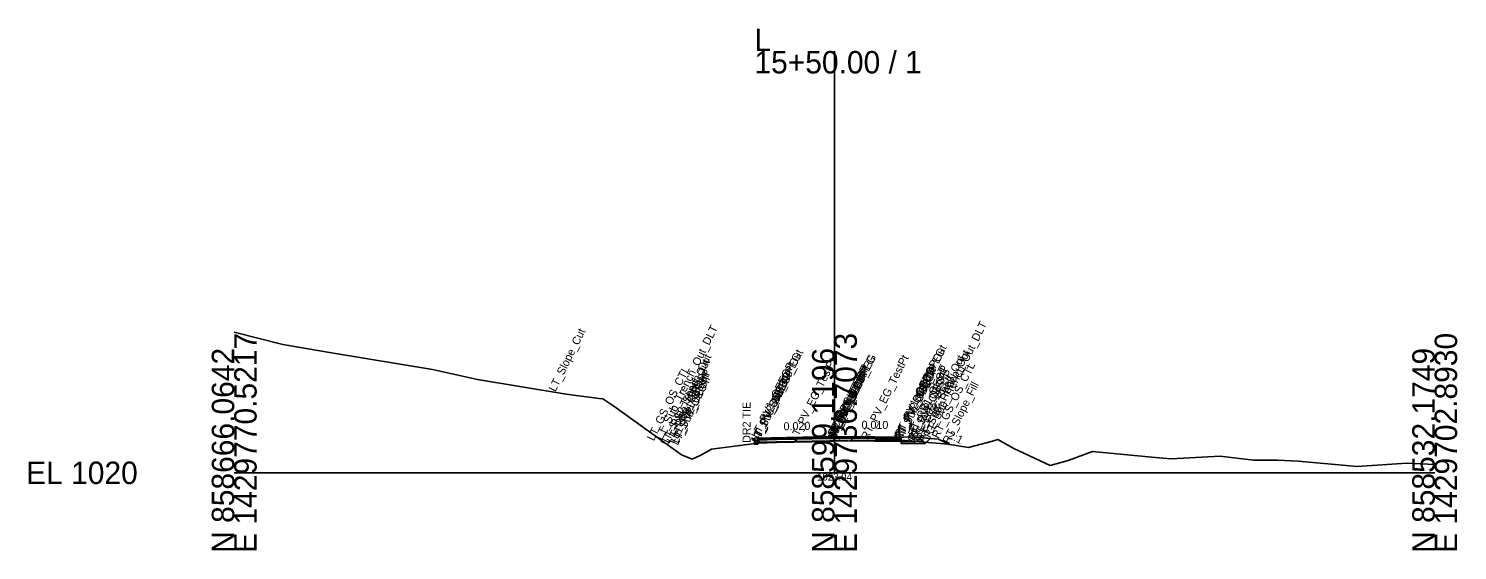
# Model space of a CAD drawing. Extents: x -26 to 153, y -10 to 13058.
# Drawn here: x -25.7 to 152.8, y 7990.3 to 8055.5 of the extents above; entities that cross this region are included whole.
import ezdxf

# ---------------------------------------------------------------- set-up
doc = ezdxf.new("R2010")
doc.units = 0
for name, color, linetype in [('Default', 7, 'Continuous'), ('Exist Cross Section Cell', 7, 'Continuous'), ('Exist XS Center Line Elevation Label', 7, 'Continuous'), ('Exist XS Ground Line', 7, 'Continuous'), ('Prop CMT Pvmt Course 1', 7, 'Continuous'), ('Prop CMT Pvmt Course 1 Wedge', 7, 'Continuous'), ('Prop CMT Pvmt Course 2', 7, 'Continuous'), ('Prop CMT Pvmt Course 2 Wedge', 7, 'Continuous'), ('Prop CMT Pvmt Surface', 7, 'Continuous'), ('Prop CMT Pvmt Surface Shoulder', 7, 'Continuous'), ('Prop CMT Pvmt Wedge Surface 1', 7, 'Continuous'), ('Prop CMT Pvmt Wedge Surface 2', 7, 'Continuous'), ('Prop CMT Shld Paved Course 1', 7, 'Continuous'), ('Prop CMT Shld Paved Course 2', 7, 'Continuous'), ('Prop CMT Slope Grass', 7, 'Continuous'), ('Prop CMT Subgrade Earthwork', 7, 'Continuous'), ('Prop XS Dump Level', 7, 'Continuous'), ('Prop XS SE Text', 7, 'Continuous'), ('Prop XS Side Slope Text', 7, 'Continuous'), ('Prop XSC Text', 7, 'Continuous')]:
    doc.layers.add(name, color=color, linetype=linetype)

msp = doc.modelspace()

# ---------------------------------------------------------------- linework, layer by layer
at = {"layer": 'Exist Cross Section Cell'}
for p, q in [((75, 8000), (75, 8052.69)), ((0, 8000), (75, 8000)), ((75, 8000), (150, 8000))]:
    msp.add_line(p, q, dxfattribs=at)
at = {"layer": 'Exist XS Ground Line'}
msp.add_lwpolyline([(0, 8017.56), (6.09, 8016.04), (12.14, 8014.99), (24.78, 8012.9), (30.42, 8011.64), (41.48, 8009.84), (45.59, 8009.28), (46.05, 8009.25), (47.45, 8008.32), (55.89, 8002.24), (57.23, 8001.69), (58.31, 8002.21), (59.63, 8002.97), (62.85, 8003.39), (65.44, 8003.71), (67.74, 8003.79), (74.37, 8003.92), (75, 8003.94), (76.86, 8003.99), (83.31, 8004.08), (89.18, 8003.56), (91.75, 8003.15), (94.74, 8003.97), (95.43, 8004.17), (97.42, 8003.03), (101.94, 8000.92), (104.21, 8001.52), (107.25, 8002.67), (115.54, 8001.88), (117.09, 8001.76), (123.2, 8002.08), (127.37, 8001.6), (130.36, 8001.57), (132.94, 8001.47), (140.33, 8000.79), (146.53, 8001.19), (150, 8001.05)], dxfattribs=at)
at = {"layer": 'Prop CMT Pvmt Course 1'}
for points in [[(75, 8004.54), (65, 8004.34)], [(65, 8004.34), (65, 8003.8)], [(65, 8003.8), (65.44, 8003.81)], [(65.44, 8004.23), (75, 8004.42)], [(65.44, 8003.81), (65.44, 8004.23)], [(75, 8004), (75, 8004.54)], [(75, 8004.54), (85, 8004.44)], [(75, 8004), (75, 8004.54)], [(75, 8004.42), (75, 8004), (75, 8004)], [(83.32, 8004.34), (75, 8004.42)], [(75, 8004.42), (75, 8004), (75, 8004)], [(83.32, 8003.92), (83.32, 8004.34)], [(85, 8003.9), (83.32, 8003.92)], [(85, 8004.44), (85, 8003.9)]]:
    msp.add_lwpolyline(points, dxfattribs=at)
at = {"layer": 'Prop CMT Pvmt Course 1 Wedge'}
for points in [[(65.44, 8004.23), (67.74, 8004.27), (74.37, 8004.41), (75, 8004.42)], [(75, 8004.29), (74.37, 8004.28), (67.74, 8004.15), (65.44, 8004.1)], [(65.44, 8004.1), (65.44, 8004.23)], [(75, 8004.42), (75, 8004.29)], [(75, 8004.42), (76.86, 8004.4), (83.31, 8004.34), (83.32, 8004.34)], [(75, 8004.29), (75, 8004.42)], [(83.32, 8004.21), (83.31, 8004.21), (76.86, 8004.28), (75, 8004.29)], [(83.32, 8004.34), (83.32, 8004.21)]]:
    msp.add_lwpolyline(points, dxfattribs=at)
at = {"layer": 'Prop CMT Pvmt Course 2'}
for points in [[(65.44, 8003.81), (65, 8003.8)], [(65, 8003.8), (65, 8003.55)], [(65.44, 8003.56), (65.44, 8003.81)], [(83.32, 8003.67), (83.32, 8003.92)], [(83.32, 8003.92), (85, 8003.9)], [(85, 8003.65), (83.32, 8003.67)], [(85, 8003.9), (85, 8003.65)], [(65, 8003.55), (65.44, 8003.56)]]:
    msp.add_lwpolyline(points, dxfattribs=at)
at = {"layer": 'Prop CMT Pvmt Course 2 Wedge'}
for points in [[(65.44, 8003.81), (67.74, 8003.86), (74.37, 8003.99), (75, 8004)], [(75, 8003.94), (74.37, 8003.92), (67.74, 8003.79), (65.44, 8003.71)], [(65.44, 8003.71), (65.44, 8003.81)], [(75, 8004), (75, 8003.94)], [(75, 8004), (76.68, 8003.99)], [(75, 8003.94), (75, 8004)], [(76.68, 8003.99), (75, 8003.94)]]:
    msp.add_lwpolyline(points, dxfattribs=at)
at = {"layer": 'Prop CMT Pvmt Surface'}
for points in [[(75, 8004.54), (65, 8004.34)], [(75, 8004.54), (85, 8004.44)]]:
    msp.add_lwpolyline(points, dxfattribs=at)
at = {"layer": 'Prop CMT Pvmt Surface Shoulder'}
for points in [[(65, 8004.34), (65, 8004.34)], [(85, 8004.44), (85, 8004.44)]]:
    msp.add_lwpolyline(points, dxfattribs=at)
at = {"layer": 'Prop CMT Pvmt Wedge Surface 1'}
for points in [[(65, 8003.8), (65, 8004.34)], [(65.44, 8003.81), (65, 8003.8)], [(75, 8004.42), (65.44, 8004.23)], [(65.44, 8004.23), (65.44, 8003.81)], [(75, 8004.54), (75, 8004), (75, 8004), (75, 8004.42)], [(75, 8004.54), (75, 8004), (75, 8004), (75, 8004.42)], [(75, 8004.42), (83.32, 8004.34)], [(83.32, 8004.34), (83.32, 8003.92)], [(83.32, 8003.92), (85, 8003.9)], [(85, 8003.9), (85, 8004.44)]]:
    msp.add_lwpolyline(points, dxfattribs=at)
at = {"layer": 'Prop CMT Pvmt Wedge Surface 2'}
for points in [[(65, 8003.8), (65, 8004.34)], [(75, 8004), (65, 8003.8)], [(75, 8004.54), (75, 8004)], [(75, 8004.54), (75, 8004)], [(75, 8004), (85, 8003.9)], [(85, 8003.9), (85, 8004.44)]]:
    msp.add_lwpolyline(points, dxfattribs=at)
at = {"layer": 'Prop CMT Shld Paved Course 1'}
for points in [[(65, 8004.34), (65, 8004.34)], [(65, 8003.8), (65, 8004.34)], [(85, 8004.44), (85, 8004.44)], [(85, 8004.44), (85.55, 8003.89)], [(85, 8003.9), (85, 8004.44)], [(85.55, 8003.89), (85, 8003.9)]]:
    msp.add_lwpolyline(points, dxfattribs=at)
at = {"layer": 'Prop CMT Shld Paved Course 2'}
for points in [[(65, 8003.55), (65, 8003.8)], [(85, 8003.9), (85.55, 8003.89), (86.05, 8003.88), (86.31, 8003.63)], [(85, 8003.65), (85, 8003.9)], [(86.31, 8003.63), (85, 8003.65)]]:
    msp.add_lwpolyline(points, dxfattribs=at)
at = {"layer": 'Prop CMT Slope Grass'}
for points in [[(85, 8004.44), (88, 8004.2)], [(88, 8004.2), (89.34, 8003.53)]]:
    msp.add_lwpolyline(points, dxfattribs=at)
at = {"layer": 'Prop CMT Subgrade Earthwork'}
for points in [[(65.44, 8003.56), (65.46, 8003.71)], [(83.32, 8003.67), (83.3, 8004.08)], [(83.32, 8003.67), (85, 8003.65)], [(85, 8003.65), (86.31, 8003.63)], [(86.31, 8003.63), (86.97, 8004.29)], [(65.44, 8003.56), (65, 8003.55)]]:
    msp.add_lwpolyline(points, dxfattribs=at)

# ---------------------------------------------------------------- texts
at = {"layer": 'Default'}
msp.add_text('-', height=0.0001, dxfattribs=at).set_placement((0, 8000))
at = {"layer": 'Exist Cross Section Cell'}
for s, p in [('L', (65, 8052.69)), ('15+50.00 / 1', (65, 8049.89)), ('EL 1020', (-26, 7998.6))]:
    msp.add_text(s, height=2.8, dxfattribs=at).set_placement(p)
for s, p in [('E 1429770.5217', (2.8, 7990)), ('E 1429736.7073', (77.8, 7990)), ('E 1429702.8930', (152.8, 7990)), ('N 858666.0642', (0, 7990)), ('N 858599.1196', (75, 7990)), ('N 858532.1749', (150, 7990))]:
    msp.add_text(s, height=2.8, rotation=90, dxfattribs=at).set_placement(p)
at = {"layer": 'Exist XS Center Line Elevation Label'}
msp.add_text('1023.94', height=0.9, dxfattribs=at).set_placement((72.83, 7999.04))
msp.add_text('1023.94', height=0.9, dxfattribs=at).set_placement((72.83, 7999.04))
msp.add_text('1023.94', height=0.9, dxfattribs=at).set_placement((72.83, 7999.04))
at = {"layer": 'Prop XS Dump Level'}
for s, p in [('LT_Slope_Cut', (40.12, 8010.06)), ('LT_Slope_Cut', (40.12, 8010.06)), ('LT_Sub_Trench_Out_DLT', (53.45, 8004)), ('RT_Sub_Trench_Out_DLT', (86.97, 8004.29)), ('LT_Sub_Trench_Out', (54.11, 8003.34)), ('LT_PV_OEEOP_EG', (65.44, 8003.71)), ('LT_PV_Sub_Tie_Out', (65.46, 8003.71)), ('LT_PV_EG_TestPt', (70.22, 8003.84)), ('RT_PV_IEEOP_EG', (75, 8003.94)), ('LT_PV_IEEOP_EG', (75, 8003.94)), ('RT_PV_EG_TestPt', (79.16, 8004.02)), ('RT_PV_Sub_Tie_Out', (83.3, 8004.08)), ('RT_PV_OEEOP_EG', (83.32, 8004.08)), ('RT_PS2_Shelf_Out', (86.05, 8003.88)), ('RT_Sub_Trench_Out', (86.31, 8003.63)), ('LT_GS_OS_CTL', (52.42, 8003.91)), ('LT_PS2_Shelf_Out', (54.36, 8003.59)), ('LT_PV1_OEOT', (55.42, 8004.15)), ('LT_PS1_OEOP', (55.42, 8004.15)), ('LT_PV1_OEEOP', (65.44, 8004.23)), ('LT_PV2_OEEOP', (65.44, 8003.81)), ('LT_Sub_OEEOP', (65.44, 8003.56)), ('RT_PV1_IEEOP', (75, 8004.42)), ('LT_PV1_IEEOP', (75, 8004.42)), ('RT_PV2_IEEOP', (75, 8004)), ('LT_PV2_IEEOP', (75, 8004)), ('RT_PV1_OEEOP', (83.32, 8004.34)), ('RT_PV2_OEEOP', (83.32, 8003.92)), ('RT_Sub_OEEOP', (83.32, 8003.67)), ('RT_PV1_OEOT', (85, 8004.44)), ('RT_PS1_OEOP', (85, 8004.44)), ('RT_PV2_OEOT', (85, 8003.9)), ('RT_PS2_OEOP', (85.55, 8003.89)), ('RT_GS_OS_CTL', (88, 8004.2)), ('LT_PS2_OEOP', (54.86, 8003.6)), ('LT_PV2_OEOT', (55.42, 8003.61)), ('LT_Sub_OEOT', (55.42, 8003.36)), ('RT_Sub_OEOT', (85, 8003.65)), ('RT_Slope_Fill', (89.34, 8003.53)), ('PV1_PGL', (75, 8004.54)), ('PV2_PGL', (75, 8004))]:
    msp.add_text(s, height=1, rotation=63.5833, dxfattribs=at).set_placement(p)
at = {"layer": 'Prop XS SE Text'}
for s, rotation, p in [('0.020', 1.1458, (68.65, 8005.31)), ('0.010', 359.4271, (78.38, 8005.51))]:
    msp.add_text(s, height=1, rotation=rotation, dxfattribs=at).set_placement(p)
at = {"layer": 'Prop XS Side Slope Text'}
msp.add_text('2:1', height=1, rotation=333.4349, dxfattribs=at).set_placement((89.11, 8004.4))
at = {"layer": 'Prop XSC Text'}
msp.add_text('DR2 TIE', height=1, rotation=90, dxfattribs=at).set_placement((64.52, 8003.74))

doc.saveas('drawing.dxf')
